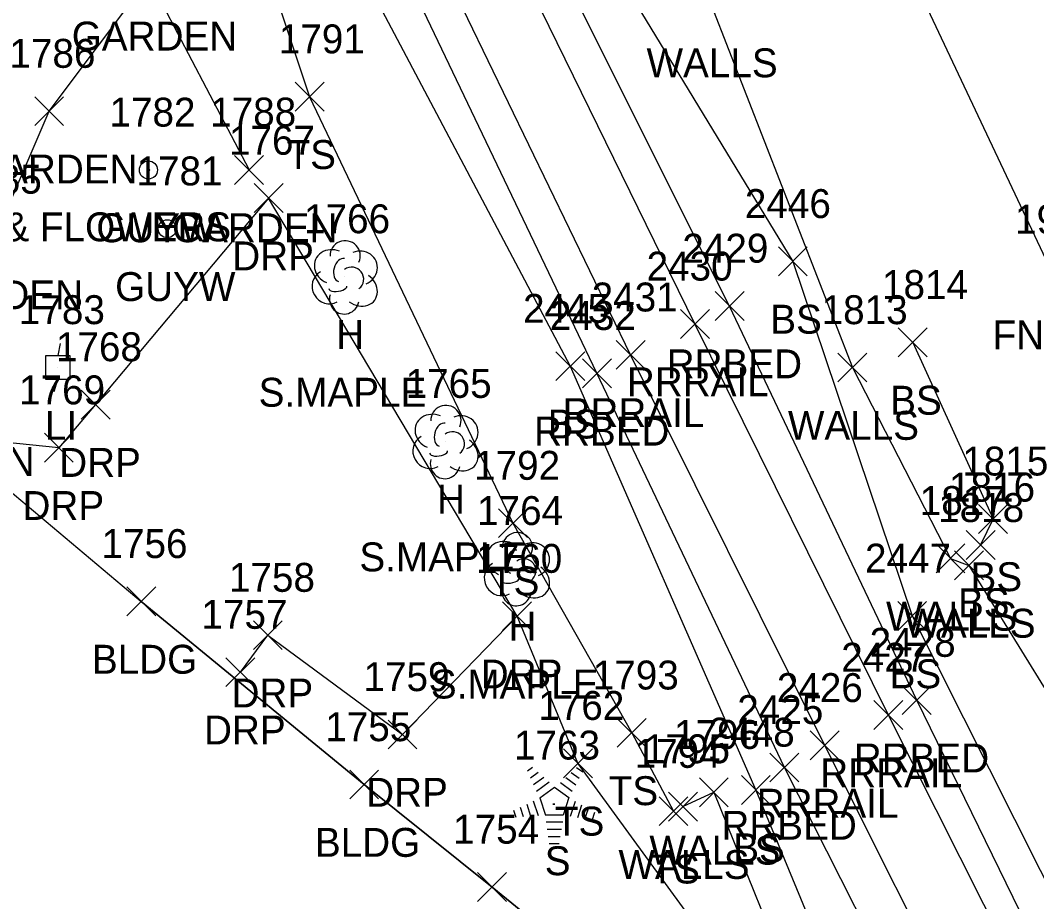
# Model space of a CAD drawing. Extents: x 1462668 to 1465147, y 550359 to 557351.
# Drawn here: x 1464582.5 to 1464652.8, y 552731.2 to 552792.1 of the extents above; entities that cross this region are included whole.
import ezdxf

# ---------------------------------------------------------------- set-up
doc = ezdxf.new("R2010")
doc.units = 0
for name, color, linetype in [('L_A', 7, 'Continuous'), ('L_C', 7, 'Continuous'), ('L_I', 7, 'Continuous'), ('L_TIC', 7, 'Continuous'), ('LAPB', 7, 'Continuous'), ('LBC', 7, 'Continuous'), ('LELB', 7, 'Continuous'), ('Level 6', 7, 'Continuous'), ('LFNC', 7, 'Continuous'), ('LTC', 7, 'Continuous'), ('LTD', 7, 'Continuous'), ('LWS', 7, 'Continuous'), ('R_A', 7, 'Continuous'), ('R_I', 7, 'Continuous'), ('R_TIC', 7, 'Continuous'), ('RDP', 7, 'Continuous'), ('RR', 7, 'Continuous'), ('RRB', 7, 'Continuous'), ('U_A', 7, 'Continuous'), ('U_I', 7, 'Continuous'), ('ULP', 7, 'Continuous'), ('UPGW', 7, 'Continuous')]:
    doc.layers.add(name, color=color, linetype=linetype)

msp = doc.modelspace()

# ---------------------------------------------------------------- linework, layer by layer
at = {"layer": 'L_TIC'}
for points in [[(1464601.504, 552785.853), (1464603.504, 552787.853)], [(1464603.504, 552785.853), (1464601.504, 552787.853)], [(1464583.496, 552784.852), (1464585.496, 552786.852)], [(1464585.496, 552784.852), (1464583.496, 552786.852)], [(1464597.324, 552780.79), (1464599.324, 552782.79)], [(1464599.324, 552780.79), (1464597.324, 552782.79)], [(1464634.924, 552774.462), (1464636.924, 552776.462)], [(1464636.924, 552774.462), (1464634.924, 552776.462)], [(1464643.218, 552768.857), (1464645.218, 552770.857)], [(1464645.218, 552768.857), (1464643.218, 552770.857)], [(1464619.531, 552767.212), (1464621.531, 552769.212)], [(1464621.531, 552767.212), (1464619.531, 552769.212)], [(1464639.043, 552767.12), (1464641.043, 552769.12)], [(1464641.043, 552767.12), (1464639.043, 552769.12)], [(1464648.773, 552756.651), (1464650.773, 552758.651)], [(1464650.773, 552756.651), (1464648.773, 552758.651)], [(1464615.573, 552756.355), (1464617.573, 552758.355)], [(1464617.573, 552756.355), (1464615.573, 552758.355)], [(1464647.909, 552754.845), (1464649.909, 552756.845)], [(1464649.909, 552754.845), (1464647.909, 552756.845)], [(1464645.829, 552753.919), (1464647.829, 552755.919)], [(1464647.829, 552753.919), (1464645.829, 552755.919)], [(1464647.101, 552753.433), (1464649.101, 552755.433)], [(1464649.101, 552753.433), (1464647.101, 552755.433)], [(1464589.863, 552750.941), (1464591.863, 552752.941)], [(1464591.863, 552750.941), (1464589.863, 552752.941)], [(1464643.18, 552749.936), (1464645.18, 552751.936)], [(1464645.18, 552749.936), (1464643.18, 552751.936)], [(1464623.782, 552741.85), (1464625.782, 552743.85)], [(1464625.782, 552741.85), (1464623.782, 552743.85)], [(1464620.064, 552739.744), (1464622.064, 552741.744)], [(1464622.064, 552739.744), (1464620.064, 552741.744)], [(1464605.284, 552738.275), (1464607.284, 552740.275)], [(1464607.284, 552738.275), (1464605.284, 552740.275)], [(1464629.463, 552737.737), (1464631.463, 552739.737)], [(1464631.463, 552737.737), (1464629.463, 552739.737)], [(1464632.366, 552737.896), (1464634.366, 552739.896)], [(1464634.366, 552737.896), (1464632.366, 552739.896)], [(1464626.676, 552736.431), (1464628.676, 552738.431)], [(1464628.676, 552736.431), (1464626.676, 552738.431)], [(1464627.323, 552736.747), (1464629.323, 552738.747)], [(1464629.323, 552736.747), (1464627.323, 552738.747)], [(1464614.125, 552731.186), (1464616.125, 552733.186)], [(1464616.125, 552731.186), (1464614.125, 552733.186)]]:
    msp.add_lwpolyline(points, dxfattribs=at)
at = {"layer": 'LAPB'}
msp.add_lwpolyline([(1464577.377, 552765.621), (1464580.729, 552777.148), (1464584.496, 552785.852), (1464591.39, 552795.047), (1464598.324, 552781.79)], dxfattribs=at)
at = {"layer": 'LBC'}
msp.add_lwpolyline([(1464631.192, 552706.177), (1464637.416, 552713.844), (1464637.452, 552714.014), (1464615.125, 552732.186), (1464606.284, 552739.275), (1464590.863, 552751.941)], dxfattribs=at)
at = {"layer": 'LELB'}
for points in [[(1464605.992, 552829.954), (1464617.903, 552805.102), (1464635.924, 552775.462), (1464644.18, 552750.936), (1464670.761, 552698.112)], [(1464591.837, 552823.151), (1464604.584, 552798.4), (1464620.531, 552768.212), (1464633.366, 552738.896), (1464646.04, 552708.211), (1464657.171, 552677.902), (1464659.575, 552669.465), (1464660.96, 552669.665)], [(1464586.679, 552819.048), (1464598.233, 552799.631), (1464602.504, 552786.853), (1464616.573, 552757.355), (1464624.782, 552742.85), (1464627.676, 552737.431)], [(1464644.218, 552769.857), (1464649.773, 552757.651), (1464648.909, 552755.845)], [(1464621.064, 552740.744), (1464616.857, 552750.919)], [(1464633.174, 552724.102), (1464621.064, 552740.744)]]:
    msp.add_lwpolyline(points, dxfattribs=at)
at = {"layer": 'Level 6'}
msp.add_lwpolyline([(1464545.725, 552864.479), (1464558.751, 552825.82), (1464570.023, 552780.164), (1464571.191, 552773.363), (1464572.36, 552766.561), (1464577.258, 552763.364), (1464590.863, 552751.941), (1464606.284, 552739.275), (1464615.125, 552732.186), (1464637.452, 552714.014)], dxfattribs=at)
at = {"layer": 'LFNC'}
msp.add_lwpolyline([(1464622.755, 552840.374), (1464640.528, 552802.915), (1464653.99, 552774.381), (1464678.707, 552725.755), (1464681.909, 552714.313)], dxfattribs=at)
at = {"layer": 'LTC'}
for p, q in [((1464617.577, 552740.212), (1464617.932, 552740.47)), ((1464620.975, 552740.453), (1464621.395, 552740.148)), ((1464617.787, 552739.747), (1464618.316, 552740.131)), ((1464617.996, 552739.281), (1464618.7, 552739.792)), ((1464620.233, 552739.756), (1464620.913, 552739.262)), ((1464620.604, 552740.104), (1464621.154, 552739.705)), ((1464618.206, 552738.815), (1464619.084, 552739.453)), ((1464618.43, 552738.36), (1464619.442, 552739.095)), ((1464619.442, 552739.095), (1464620.439, 552738.37)), ((1464619.862, 552739.408), (1464620.672, 552738.819)), ((1464617.976, 552738.141), (1464618.307, 552737.122)), ((1464618.43, 552738.36), (1464618.818, 552737.167)), ((1464620.439, 552738.37), (1464620.048, 552737.167)), ((1464620.877, 552738.099), (1464620.539, 552737.059)), ((1464616.61, 552737.491), (1464616.762, 552737.024)), ((1464617.065, 552737.708), (1464617.277, 552737.056)), ((1464617.52, 552737.925), (1464617.792, 552737.089)), ((1464621.321, 552737.849), (1464621.034, 552736.964)), ((1464621.766, 552737.599), (1464621.529, 552736.869)), ((1464620.048, 552737.167), (1464618.818, 552737.167)), ((1464620.01, 552736.667), (1464618.865, 552736.667)), ((1464622.21, 552737.348), (1464622.023, 552736.774)), ((1464619.926, 552736.167), (1464618.938, 552736.167)), ((1464619.842, 552735.667), (1464619.01, 552735.667)), ((1464619.758, 552735.167), (1464619.083, 552735.167))]:
    msp.add_line(p, q, dxfattribs=at)
at = {"layer": 'LTD'}
for p, q in [((1464604.921, 552774.409), (1464604.921, 552774.409)), ((1464604.921, 552774.409), (1464604.921, 552774.409)), ((1464611.889, 552763.02), (1464611.889, 552763.02)), ((1464611.889, 552763.02), (1464611.889, 552763.02)), ((1464616.83, 552754.226), (1464616.83, 552754.226)), ((1464616.83, 552754.226), (1464616.83, 552754.226))]:
    msp.add_line(p, q, dxfattribs=at)
for centre in [(1464604.968, 552775.843), (1464611.935, 552764.454), (1464616.877, 552755.66)]:
    msp.add_arc(centre, 1.047, 335.52715, 180.95627, dxfattribs=at)
for centre, major_axis, ratio, start_param, end_param in [((1464604.129, 552775.076), (1.21, -0.512), 0.895232, 1.570796, 4.712389), ((1464605.963, 552774.993), (-1.141, -0.483), 0.949671, 1.570796, 4.712389), ((1464604.713, 552774.868), (-0.208, -0.792), 0.645439, 3.141593, 6.283185), ((1464603.838, 552773.701), (0.584, -1.042), 0.959034, 3.141593, 6.283185), ((1464605.421, 552774.243), (-0.5, 0.667), 0.989748, 3.141593, 6.283185), ((1464605.921, 552773.576), (-1.09, 0.792), 0.841452, 1.570796, 4.712389), ((1464604.463, 552773.659), (-0.625, -0.083), 0.423636, 0, 3.141593), ((1464604.921, 552772.909), (0.265, 1.061), 0.942809, 1.570796, 4.712389), ((1464611.097, 552763.686), (1.21, -0.512), 0.895232, 1.570796, 4.712389), ((1464612.93, 552763.603), (-1.141, -0.483), 0.949671, 1.570796, 4.712389), ((1464611.68, 552763.478), (-0.208, -0.792), 0.645439, 3.141593, 6.283185), ((1464612.389, 552762.853), (-0.5, 0.667), 0.989748, 3.141593, 6.283185), ((1464610.806, 552762.311), (0.584, -1.042), 0.959034, 3.141593, 6.283185), ((1464612.889, 552762.187), (-1.09, 0.792), 0.841452, 1.570796, 4.712389), ((1464611.431, 552762.27), (-0.625, -0.083), 0.423636, 0, 3.141593), ((1464611.889, 552761.52), (0.265, 1.061), 0.942809, 1.570796, 4.712389), ((1464616.038, 552754.893), (1.21, -0.512), 0.895232, 1.570796, 4.712389), ((1464617.871, 552754.81), (-1.141, -0.483), 0.949671, 1.570796, 4.712389), ((1464616.621, 552754.684), (-0.208, -0.792), 0.645439, 3.141593, 6.283185), ((1464617.33, 552754.06), (-0.5, 0.667), 0.989748, 3.141593, 6.283185), ((1464615.747, 552753.518), (0.584, -1.042), 0.959034, 3.141593, 6.283185), ((1464617.83, 552753.393), (-1.09, 0.792), 0.841452, 1.570796, 4.712389), ((1464616.372, 552753.476), (-0.625, -0.083), 0.423636, 0, 3.141593), ((1464616.83, 552752.726), (0.265, 1.061), 0.942809, 1.570796, 4.712389)]:
    msp.add_ellipse(centre, major_axis=major_axis, ratio=ratio, start_param=start_param, end_param=end_param, dxfattribs=at)
at = {"layer": 'LWS'}
for points in [[(1464627.227, 552807.88), (1464624.579, 552807.197), (1464630.268, 552793.197), (1464640.043, 552768.12), (1464646.829, 552754.919), (1464648.101, 552754.433), (1464659.033, 552736.713), (1464665.52, 552721.715), (1464672.421, 552707.566), (1464674.293, 552701.543), (1464673.431, 552699.034)], [(1464628.323, 552737.747), (1464630.463, 552738.737), (1464636.481, 552723.859), (1464640.409, 552715.693), (1464643.848, 552708.405), (1464644.066, 552707.906), (1464644.246, 552705.998), (1464645.171, 552703.317), (1464649.444, 552691.071), (1464655.056, 552674.447), (1464657.686, 552668.432), (1464659.187, 552668.867)]]:
    msp.add_lwpolyline(points, dxfattribs=at)
at = {"layer": 'R_TIC'}
for points in [[(1464598.672, 552778.84), (1464600.672, 552780.84)], [(1464600.672, 552778.84), (1464598.672, 552780.84)], [(1464630.556, 552771.375), (1464632.556, 552773.375)], [(1464632.556, 552771.375), (1464630.556, 552773.375)], [(1464628.159, 552770.135), (1464630.159, 552772.135)], [(1464630.159, 552770.135), (1464628.159, 552772.135)], [(1464623.708, 552767.998), (1464625.708, 552769.998)], [(1464625.708, 552767.998), (1464623.708, 552769.998)], [(1464621.383, 552766.72), (1464623.383, 552768.72)], [(1464623.383, 552766.72), (1464621.383, 552768.72)], [(1464586.705, 552764.556), (1464588.705, 552766.556)], [(1464588.705, 552764.556), (1464586.705, 552766.556)], [(1464584.165, 552761.574), (1464586.165, 552763.574)], [(1464586.165, 552761.574), (1464584.165, 552763.574)], [(1464615.857, 552749.919), (1464617.857, 552751.919)], [(1464617.857, 552749.919), (1464615.857, 552751.919)], [(1464598.622, 552748.606), (1464600.622, 552750.606)], [(1464600.622, 552748.606), (1464598.622, 552750.606)], [(1464596.72, 552746.048), (1464598.72, 552748.048)], [(1464598.72, 552746.048), (1464596.72, 552748.048)], [(1464643.495, 552744.11), (1464645.495, 552746.11)], [(1464645.495, 552744.11), (1464643.495, 552746.11)], [(1464641.534, 552743.081), (1464643.534, 552745.081)], [(1464643.534, 552743.081), (1464641.534, 552745.081)], [(1464607.934, 552741.737), (1464609.934, 552743.737)], [(1464609.934, 552741.737), (1464607.934, 552743.737)], [(1464637.134, 552740.98), (1464639.134, 552742.98)], [(1464639.134, 552740.98), (1464637.134, 552742.98)], [(1464634.344, 552739.456), (1464636.344, 552741.456)], [(1464636.344, 552739.456), (1464634.344, 552741.456)]]:
    msp.add_lwpolyline(points, dxfattribs=at)
at = {"layer": 'RDP'}
msp.add_lwpolyline([(1464597.72, 552747.048), (1464599.622, 552749.606), (1464608.934, 552742.737), (1464616.857, 552750.919), (1464599.672, 552779.84), (1464587.705, 552765.556), (1464585.165, 552762.574), (1464577.258, 552763.364), (1464572.36, 552766.561), (1464570.023, 552780.164), (1464570.141, 552783.231), (1464571.892, 552786.35), (1464578.166, 552790.524), (1464569.523, 552814.012)], dxfattribs=at)
at = {"layer": 'RR'}
for points in [[(1464849.389, 552249.534), (1464842.819, 552270.793), (1464835.11, 552294.838), (1464826.262, 552322.52), (1464813.909, 552358.251), (1464808.668, 552373.872), (1464804.992, 552384.746), (1464790.19, 552425.007), (1464777.181, 552458.665), (1464762.364, 552494.605), (1464744.909, 552535.145), (1464735.628, 552555.847), (1464721.293, 552586.6), (1464702.021, 552626.346), (1464686.842, 552656.687), (1464671.35, 552687.141), (1464662.335, 552704.74), (1464642.534, 552744.081), (1464629.159, 552771.135), (1464613.477, 552803.16), (1464601.343, 552828.316)], [(1464844.813, 552247.755), (1464838.177, 552269.149), (1464830.386, 552293.617), (1464821.392, 552321.548), (1464809.517, 552356.645), (1464804.149, 552372.473), (1464800.295, 552383.078), (1464785.596, 552423.206), (1464772.719, 552456.472), (1464757.811, 552492.705), (1464740.233, 552533.386), (1464731.218, 552553.662), (1464716.736, 552584.611), (1464697.665, 552624.112), (1464682.453, 552654.497), (1464666.878, 552684.945), (1464657.727, 552702.874), (1464638.134, 552741.98), (1464624.708, 552768.998), (1464609.228, 552800.971), (1464596.703, 552826.136)]]:
    msp.add_lwpolyline(points, dxfattribs=at)
at = {"layer": 'RRB'}
for points in [[(1464851.042, 552250.445), (1464845.147, 552271.635), (1464837.544, 552295.462), (1464828.768, 552323.575), (1464816.78, 552359.11), (1464810.928, 552374.769), (1464807.843, 552386.028), (1464792.774, 552426.038), (1464778.944, 552461.754), (1464771.168, 552477.614), (1464764.619, 552495.611), (1464747.04, 552536.302), (1464737.618, 552557.165), (1464723.44, 552587.94), (1464704.535, 552627.922), (1464689.191, 552657.618), (1464673.574, 552688.335), (1464664.014, 552705.151), (1464644.495, 552745.11), (1464631.556, 552772.375), (1464615.641, 552804.178), (1464603.908, 552829.416)], [(1464842.442, 552246.931), (1464836.486, 552268.553), (1464828.066, 552292.901), (1464819.091, 552320.895), (1464807.286, 552355.87), (1464801.457, 552371.532), (1464797.599, 552381.724), (1464783.012, 552422.471), (1464769.406, 552454.584), (1464755.315, 552491.81), (1464738.611, 552532.376), (1464729.391, 552552.755), (1464715, 552583.837), (1464695.071, 552622.976), (1464679.554, 552652.995), (1464663.948, 552683.282), (1464654.855, 552701.899), (1464635.344, 552740.456), (1464622.383, 552767.72), (1464607.066, 552799.752), (1464594.744, 552825)]]:
    msp.add_lwpolyline(points, dxfattribs=at)
at = {"layer": 'ULP'}
for p, q in [((1464585.262, 552769.788), (1464585.095, 552768.955)), ((1464584.262, 552767.288), (1464584.262, 552768.955)), ((1464584.262, 552768.955), (1464585.928, 552768.955)), ((1464585.928, 552768.955), (1464585.928, 552767.288)), ((1464585.095, 552768.122), (1464585.095, 552768.122)), ((1464585.928, 552767.288), (1464584.262, 552767.288)), ((1464584.845, 552766.455), (1464585.095, 552767.288))]:
    msp.add_line(p, q, dxfattribs=at)
at = {"layer": 'UPGW'}
for centre, radius in [((1464591.36, 552781.785), 0.625), ((1464591.36, 552781.785), 0.0833), ((1464592.664, 552777.718), 0.625), ((1464592.664, 552777.718), 0.0833)]:
    msp.add_circle(centre, radius, dxfattribs=at)

# ---------------------------------------------------------------- texts
at = {"layer": 'L_A'}
for s, p in [('GARDEN', (1464586.059, 552790.047)), ('WALLS', (1464625.811, 552788.197)), ('TS', (1464600.914, 552781.853)), ('GARDEN', (1464579.165, 552780.852)), ('GARDEN', (1464592.993, 552776.79)), ('GARDEN', (1464575.398, 552772.148)), ('BS', (1464634.365, 552770.462)), ('H', (1464604.354, 552769.409)), ('FNCHL', (1464649.738, 552769.381)), ('BS', (1464642.659, 552764.857)), ('BS', (1464618.972, 552763.212)), ('WALLS', (1464635.586, 552763.12)), ('GARDEN', (1464572.047, 552760.621)), ('H', (1464611.322, 552758.02)), ('TS', (1464614.982, 552752.355)), ('BS', (1464648.214, 552752.651)), ('BS', (1464647.35, 552750.845)), ('WALLS', (1464642.372, 552749.919)), ('WALLS', (1464643.645, 552749.433)), ('H', (1464616.263, 552749.226)), ('BLDG', (1464587.453, 552746.941)), ('BS', (1464642.621, 552745.936)), ('TS', (1464623.192, 552737.85)), ('TS', (1464619.473, 552735.744)), ('BLDG', (1464602.874, 552734.275)), ('WALLS', (1464626.007, 552733.737)), ('BS', (1464631.807, 552733.896)), ('S', (1464618.768, 552733.004)), ('WALLS', (1464623.866, 552732.747)), ('TS', (1464626.085, 552732.431))]:
    msp.add_text(s, height=2, dxfattribs=at).set_placement(p)
at = {"layer": 'L_C'}
for s, p in [('SHRUBS & FLOWERS', (1464569.441, 552776.852)), ('S.MAPLE', (1464598.984, 552765.409)), ('S.MAPLE', (1464605.952, 552754.02)), ('S.MAPLE', (1464610.893, 552745.226))]:
    msp.add_text(s, height=2, dxfattribs=at).set_placement(p)
at = {"layer": 'L_I'}
for s, p in [('1791', (1464600.378, 552789.853)), ('1786', (1464581.748, 552788.852)), ('1788', (1464595.631, 552784.79)), ('1785', (1464578.036, 552780.148)), ('2446', (1464632.609, 552778.462)), ('1766', (1464602.126, 552777.409)), ('1935', (1464651.297, 552777.381)), ('1814', (1464642.092, 552772.857)), ('2445', (1464617.271, 552771.212)), ('1813', (1464637.917, 552771.12)), ('1765', (1464609.149, 552766.02)), ('1815', (1464647.647, 552760.651)), ('1792', (1464613.88, 552760.355)), ('1816', (1464646.728, 552758.845)), ('1817', (1464644.703, 552757.919)), ('1764', (1464614.09, 552757.226)), ('1818', (1464645.975, 552757.433)), ('1756', (1464588.115, 552754.941)), ('2447', (1464640.92, 552753.936)), ('1793', (1464622.09, 552745.85)), ('1762', (1464618.323, 552743.744)), ('1755', (1464603.591, 552742.275)), ('1796', (1464627.715, 552741.737)), ('2448', (1464630.106, 552741.896)), ('1763', (1464616.642, 552741.004)), ('1794', (1464624.983, 552740.431)), ('1795', (1464625.63, 552740.747)), ('1754', (1464612.432, 552735.186))]:
    msp.add_text(s, height=2, dxfattribs=at).set_placement(p)
at = {"layer": 'LTC'}
msp.add_text('.', height=1.037, rotation=270, dxfattribs=at).set_placement((1464619.325, 552738.108))
at = {"layer": 'R_A'}
for s, p in [('DRP', (1464597.16, 552774.84)), ('RRBED', (1464627.202, 552767.375)), ('RRRAIL', (1464624.45, 552766.135)), ('RRRAIL', (1464620, 552763.998)), ('RRBED', (1464618.029, 552762.72)), ('DRP', (1464585.193, 552760.556)), ('DRP', (1464582.654, 552757.574)), ('DRP', (1464614.345, 552745.919)), ('DRP', (1464597.11, 552744.606)), ('DRP', (1464595.208, 552742.048)), ('RRBED', (1464640.141, 552740.11)), ('RRRAIL', (1464637.825, 552739.081)), ('DRP', (1464606.423, 552737.737)), ('RRRAIL', (1464633.425, 552736.98)), ('RRBED', (1464630.99, 552735.456))]:
    msp.add_text(s, height=2, dxfattribs=at).set_placement(p)
at = {"layer": 'R_I'}
for s, p in [('1767', (1464596.932, 552782.84)), ('2429', (1464628.288, 552775.375)), ('2430', (1464625.812, 552774.135)), ('2431', (1464622.015, 552771.998)), ('2432', (1464619.123, 552770.72)), ('1768', (1464584.964, 552768.556)), ('1769', (1464582.417, 552765.574)), ('1760', (1464614.03, 552753.919)), ('1758', (1464596.929, 552752.606)), ('1757', (1464595.027, 552750.048)), ('2428', (1464641.236, 552748.11)), ('2427', (1464639.274, 552747.081)), ('1759', (1464606.234, 552745.737)), ('2426', (1464634.819, 552744.98)), ('2425', (1464632.084, 552743.456))]:
    msp.add_text(s, height=2, dxfattribs=at).set_placement(p)
at = {"layer": 'U_A'}
for s, p in [('GUYW', (1464587.753, 552776.785)), ('GUYW', (1464589.058, 552772.718)), ('LI', (1464584.197, 552763.122))]:
    msp.add_text(s, height=2, dxfattribs=at).set_placement(p)
at = {"layer": 'U_I'}
for s, p in [('1782', (1464588.667, 552784.785)), ('1781', (1464590.538, 552780.718)), ('1783', (1464582.402, 552771.122))]:
    msp.add_text(s, height=2, dxfattribs=at).set_placement(p)

doc.saveas('drawing.dxf')
